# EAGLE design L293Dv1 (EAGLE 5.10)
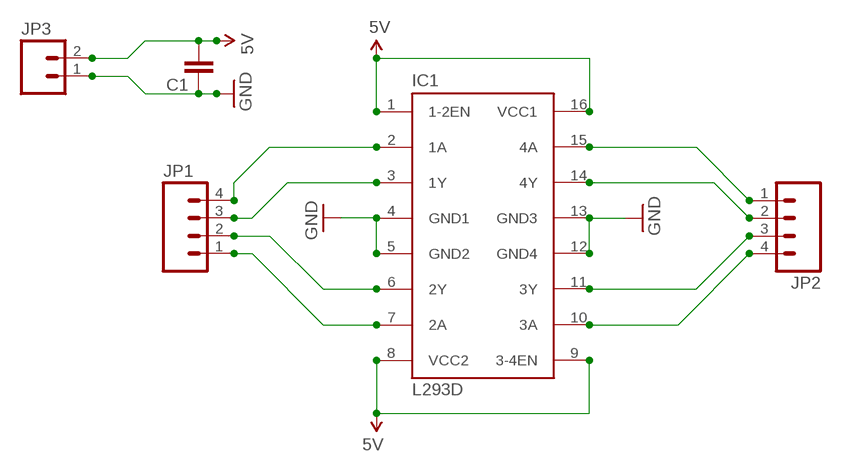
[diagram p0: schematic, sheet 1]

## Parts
C1  CAPPTH  [CAP-PTH-SMALL]
IC1  L293D  [DIL16]
JP1  M04PTH  [1X04]
JP2  M04PTH  [1X04]
JP3  M02PTH  [1X02]

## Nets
5V: C1.2 IC1.1(1-2EN) IC1.8(VCC2) IC1.9(3-4EN) IC1.16(VCC1) JP3.2
GND: C1.1 IC1.4(GND1) IC1.5(GND2) IC1.12(GND4) IC1.13(GND3) JP3.1
N$5: IC1.2(1A) JP1.4
N$6: IC1.3(1Y) JP1.3
N$7: IC1.6(2Y) JP1.2
N$8: IC1.7(2A) JP1.1
N$9: IC1.10(3A) JP2.4
N$10: IC1.11(3Y) JP2.3
N$11: IC1.14(4Y) JP2.2
N$12: IC1.15(4A) JP2.1

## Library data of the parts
C1 = SparkFun:CAP: Capacitor
IC1 = st-microelectronics:L293D: PUSH-PULL 4 CHANNEL DRIVER
JP1 JP2 = SparkFun:M04: Header 4 Standard 4-pin 0.1" header. Use with straight break away headers (SKU : PRT-00116), right angle break away headers (PRT-00553), swiss pins (PRT-00743), machine pins (PRT-00117), and female headers (PRT-00115). Molex polarized connector foot print use with SKU : PRT-08231 with associated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
JP3 = SparkFun:M02: Header 2

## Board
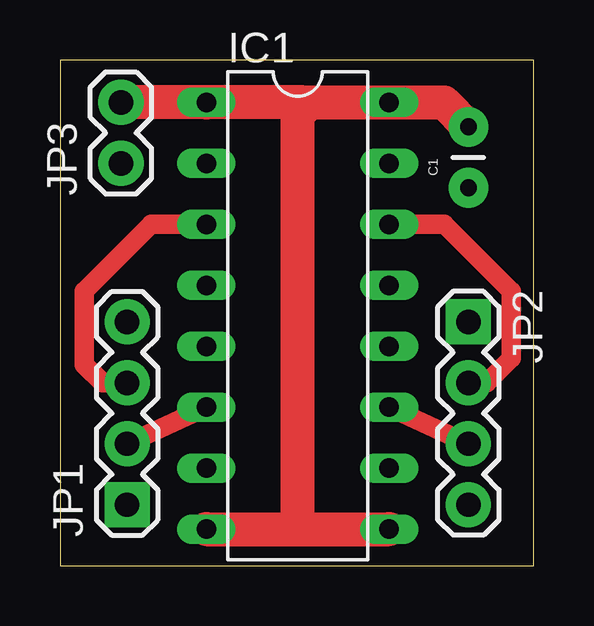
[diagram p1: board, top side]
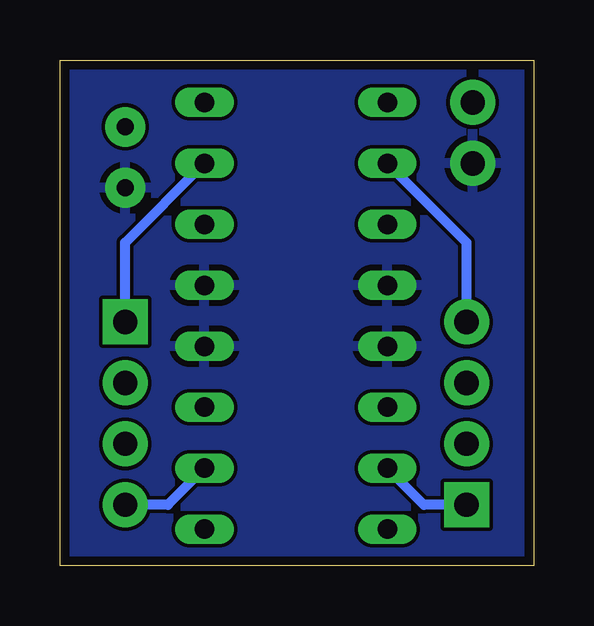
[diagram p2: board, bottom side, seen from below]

Size 19.74 x 21.07 mm. Coordinates in mm from the lower left corner, seen from the top.
Outline: 0,0 19.74,0 19.74,21.07 0,21.07 0,0
Copper layers (1*16): Top 0.0356mm / dielectric 1.5011mm / Bottom 0.0356mm
Design rules "Dorkbot": minimum track width 6mil, minimum drill 13mil, track to track 6mil, track to pad 6mil, pad to pad 6mil, via to via 6mil, smd to smd 6mil, copper to edge 15mil, drill to drill 6mil, minimum pad ring 7mil, minimum via ring 7mil, stop-mask expansion 4mil, vias tented up to drill 0mil, thermal gap 10mil

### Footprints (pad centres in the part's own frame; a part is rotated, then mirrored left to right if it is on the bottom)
CAP-PTH-SMALL = drill 0.7 pad 1.651 round: 1 0,0; 2 2.54,0
DIL16 = drill 0.813 long: 1 -8.89,-3.81; 2 -6.35,-3.81; 3 -3.81,-3.81; 4 -1.27,-3.81; 5 1.27,-3.81; 6 3.81,-3.81; 7 6.35,-3.81; 8 8.89,-3.81; 9 8.89,3.81; 10 6.35,3.81; 11 3.81,3.81; 12 1.27,3.81; 13 -1.27,3.81; 14 -3.81,3.81; 15 -6.35,3.81; 16 -8.89,3.81
1X04 = drill 1.016 pad 1.88 square: 1 0,0 | drill 1.016 pad 1.88 round: 2 2.54,0; 3 5.08,0; 4 7.62,0
1X02 = drill 1.016 pad 1.88 round: 1 0,0; 2 2.54,0

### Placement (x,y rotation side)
C1  17.02,15.75 90 top
IC1  9.91,10.41 270 top
JP1  2.79,2.54 90 top
JP2  17.02,10.16 270 top
JP3  2.54,16.76 90 top

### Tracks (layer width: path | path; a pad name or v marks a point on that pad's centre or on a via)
5V
  Top 1.422: 10.16,19.3 IC1.1 JP3.2 | 10.16,19.3 IC1.16 16,19.3 C1.2 | 9.91,1.52 IC1.9 | IC1.8 9.91,1.52 | 9.91,1.52 9.91,19.05 10.16,19.05 10.16,19.3
GND
  pour Bottom: -0.25,21.34 19.56,21.34 19.56,0 -0.25,0
N$5
  Bottom 0.406: JP1.4 2.79,13.46 IC1.2
N$6
  Top 0.813: JP1.3 1.78,7.62 1.02,8.38 1.02,11.43 3.81,14.22 IC1.3
N$7
  Top 0.813: JP1.2 IC1.6
N$8
  Bottom 0.406: JP1.1 4.57,2.54 IC1.7
N$9
  Bottom 0.406: JP2.4 15.24,2.54 IC1.10
N$10
  Top 0.813: IC1.11 JP2.3
N$11
  Top 0.813: JP2.2 17.78,7.62 18.8,8.64 18.8,11.43 16,14.22 IC1.14
N$12
  Bottom 0.406: JP2.1 17.02,13.46 IC1.15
